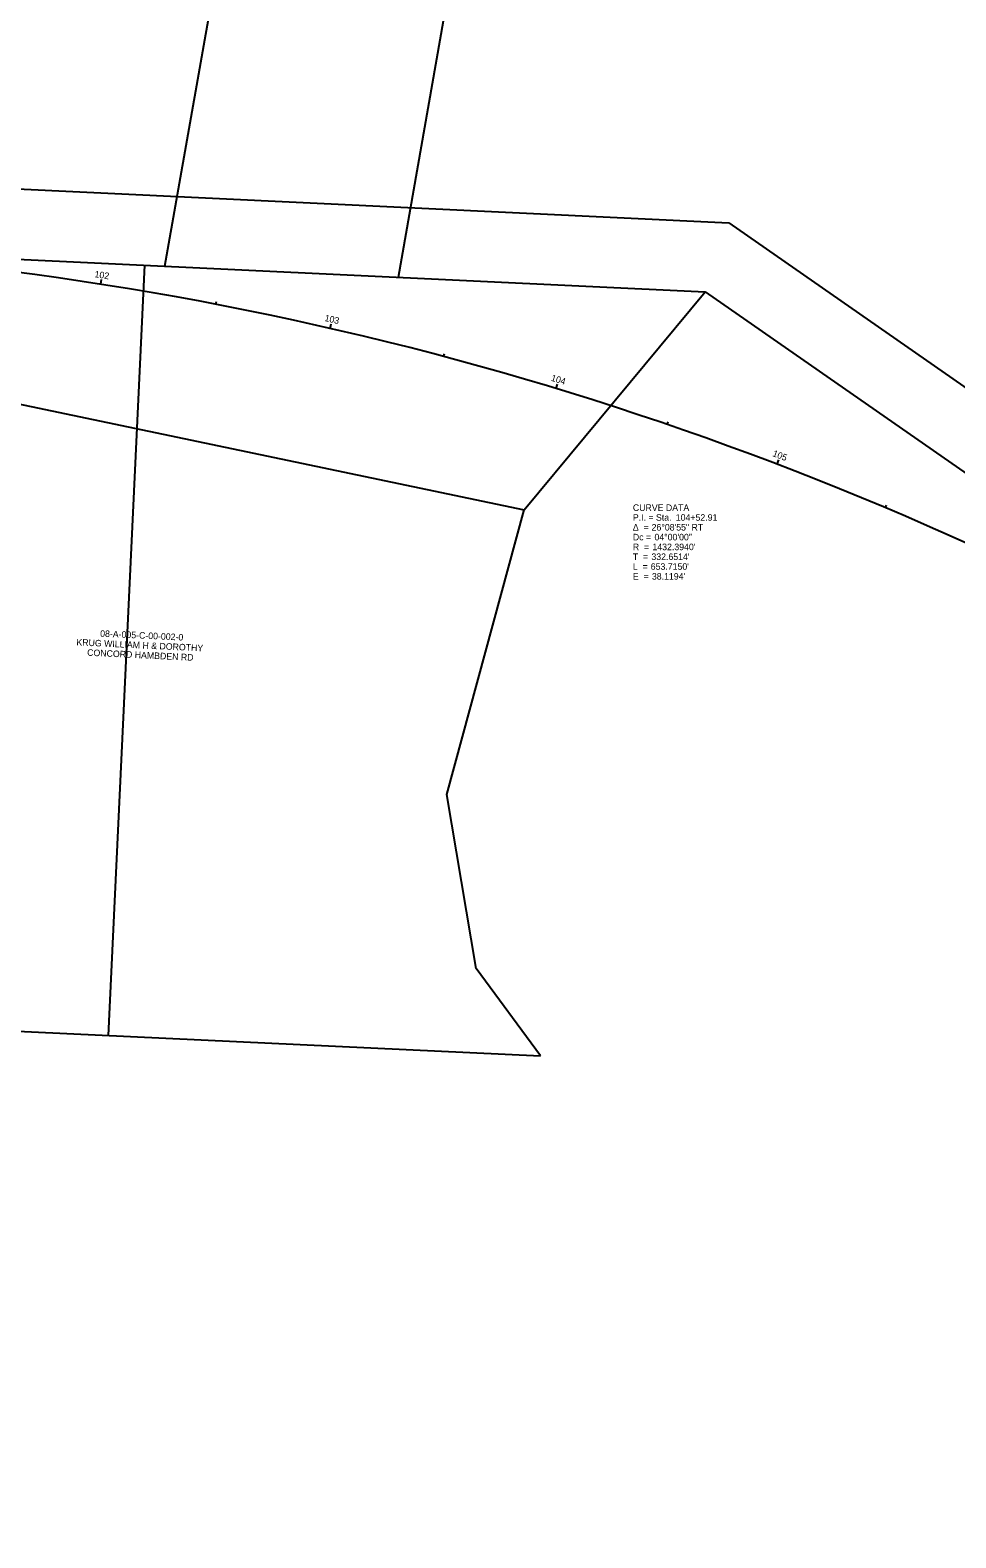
# Model space of a CAD drawing. Extents: x 2318731 to 2320621, y 732958 to 734198.
# Drawn here: x 2319505 to 2319901, y 732983 to 733629 of the extents above; entities that cross this region are included whole.
import ezdxf

# ---------------------------------------------------------------- set-up
doc = ezdxf.new("R2010")
doc.units = 0
for name, color, linetype in [('RW_X_CL_100_Stations', 7, 'Continuous'), ('RW_X_CL_500_Curve_Data', 7, 'Continuous'), ('RW_X_CL_500_Stations', 7, 'Continuous'), ('RW_X_Text', 7, 'Continuous'), ('V-SURV-IPF', 7, 'Continuous'), ('V-SURV-PARL-LINE', 7, 'Continuous'), ('V-SURV-PARL-SUBL', 7, 'Continuous'), ('V-SURV-RWAY', 7, 'Continuous'), ('V-SURV-RWAY-CNTR', 7, 'Continuous')]:
    doc.layers.add(name, color=color, linetype=linetype)

msp = doc.modelspace()

# ---------------------------------------------------------------- linework, layer by layer
at = {"layer": 'RW_X_CL_100_Stations'}
for p, q in [((2319534.81, 733519.92), (2319535.12, 733521.9)), ((2319584.06, 733511.32), (2319584.28, 733512.49)), ((2319632.98, 733501), (2319633.42, 733502.95)), ((2319681.51, 733488.98), (2319681.82, 733490.14)), ((2319729.59, 733475.27), (2319730.17, 733477.18)), ((2319777.17, 733459.89), (2319777.55, 733461.03)), ((2319824.17, 733442.87), (2319824.89, 733444.73)), ((2319870.56, 733424.21), (2319871.03, 733425.31))]:
    msp.add_line(p, q, dxfattribs=at)
at = {"layer": 'RW_X_CL_500_Stations'}
for p, q in [((2319534.81, 733519.92), (2319534.99, 733521.11)), ((2319632.98, 733501), (2319633.25, 733502.17)), ((2319729.59, 733475.27), (2319729.94, 733476.42)), ((2319824.17, 733442.87), (2319824.89, 733444.73))]:
    msp.add_line(p, q, dxfattribs=at)
at = {"layer": 'V-SURV-IPF'}
for p, q in [((2319562.24, 733527.63), (2319620.71, 733860.1)), ((2319662.12, 733522.88), (2319721.73, 733861.78)), ((2319306.05, 733539.81), (2319793.43, 733516.64)), ((2319715.9, 733423.39), (2319793.43, 733516.64)), ((2319793.43, 733516.64), (2320193.75, 733237.69)), ((2319682.8, 733301.52), (2319715.9, 733423.39)), ((2319695.46, 733227.07), (2319682.8, 733301.52)), ((2319722.93, 733189.62), (2319695.46, 733227.07)), ((2319212.39, 733213.89), (2319722.93, 733189.62))]:
    msp.add_line(p, q, dxfattribs=at)
at = {"layer": 'V-SURV-PARL-LINE'}
for p, q in [((2319427.43, 733564.08), (2319803.49, 733546.2)), ((2319803.49, 733546.2), (2320611.23, 732983.34)), ((2319302.56, 733509.94), (2319715.9, 733423.39))]:
    msp.add_line(p, q, dxfattribs=at)
at = {"layer": 'V-SURV-RWAY'}
msp.add_arc((2319312.92, 732104.82), 1432.39, 58.12986, 84.27847, dxfattribs=at)
at = {"layer": 'V-SURV-RWAY-CNTR'}
msp.add_line((2319538.03, 733198.41), (2319553.7, 733528.04), dxfattribs=at)

# ---------------------------------------------------------------- texts
at = {"layer": 'RW_X_CL_100_Stations'}
for s, rotation, p in [('102', 351.08866, (2319531.97, 733522.95)), ('103', 347.08866, (2319630.37, 733504.21)), ('104', 343.08866, (2319727.23, 733478.65)), ('105', 339.08865, (2319822.01, 733446.42))]:
    msp.add_text(s, height=2.8, rotation=rotation, dxfattribs=at).set_placement(p)
at = {"layer": 'RW_X_CL_500_Curve_Data'}
for s, p in [('CURVE DATA', (2319762.47, 733422.88)), ('Δ  = ', (2319762.47, 733414.48)), ('P.I. = Sta. ', (2319762.47, 733418.68)), ('26°08\'55" RT', (2319770.49, 733414.48)), ('104+52.91', (2319780.84, 733418.68)), ('Dc = ', (2319762.47, 733410.28)), ('04°00\'00"', (2319771.71, 733410.28)), ('T  = ', (2319762.47, 733401.88)), ('R  = ', (2319762.47, 733406.08)), ("332.6514'", (2319770.4, 733401.88)), ("1432.3940'", (2319770.84, 733406.08)), ('L  = ', (2319762.47, 733397.68)), ("653.7150'", (2319770.12, 733397.68)), ('E  = ', (2319762.47, 733393.48)), ("38.1194'", (2319770.62, 733393.48))]:
    msp.add_text(s, height=2.8, dxfattribs=at).set_placement(p)
at = {"layer": 'RW_X_CL_500_Stations'}
msp.add_text('105', height=2.8, rotation=339.08865, dxfattribs=at).set_placement((2319822.01, 733446.42))
at = {"layer": 'RW_X_Text'}
for s, p in [('08-A-005-C-00-002-0', (2319534.47, 733369.07)), ('KRUG WILLIAM H & DOROTHY', (2319524.31, 733365.34)), ('CONCORD HAMBDEN RD', (2319528.9, 733360.92))]:
    msp.add_text(s, height=2.8, rotation=357.27847, dxfattribs=at).set_placement(p)
at = {"layer": 'V-SURV-PARL-SUBL'}
for s, p in [('CURVE DATA', (2319762.47, 733422.88)), ('Δ  = ', (2319762.47, 733414.48)), ('P.I. = Sta. ', (2319762.47, 733418.68)), ('26°08\'55" RT', (2319770.49, 733414.48)), ('104+52.91', (2319780.84, 733418.68)), ('Dc = ', (2319762.47, 733410.28)), ('04°00\'00"', (2319771.71, 733410.28)), ('T  = ', (2319762.47, 733401.88)), ('R  = ', (2319762.47, 733406.08)), ("332.6514'", (2319770.4, 733401.88)), ("1432.3940'", (2319770.84, 733406.08)), ('L  = ', (2319762.47, 733397.68)), ("653.7150'", (2319770.12, 733397.68)), ('E  = ', (2319762.47, 733393.48)), ("38.1194'", (2319770.62, 733393.48))]:
    msp.add_text(s, height=2.8, dxfattribs=at).set_placement(p)

doc.saveas('drawing.dxf')
